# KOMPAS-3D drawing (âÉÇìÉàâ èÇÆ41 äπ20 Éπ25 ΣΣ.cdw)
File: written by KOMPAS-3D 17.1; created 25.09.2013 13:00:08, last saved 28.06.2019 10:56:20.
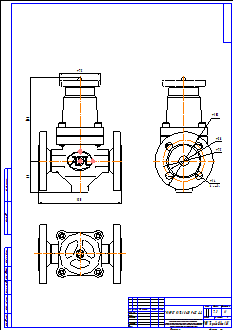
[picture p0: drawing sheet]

Sheet 1: A2, portrait

Title block, sheet 1: name: ГРАНРЕГ КАТ41 Ду20 Ру25 фф; material: Внимание! Данный продукт является объектом авторского права ООО «Торговый Дом АДЛ». / Запрещается изменение, копирование, распространение / (в том числе путем копирования на другие сайты и ресурсы в Интернете) / или любое иное использование информации и объектов без предварительного / согласия правообладателя (ООО «Торговый Дом АДЛ»).; mass: 7,3; sheets: 1; organisation: ООО "Торговый дом АДЛ"; sheet format: A2; stored path: \\adlc.lan\data\АДЛ_ПКД\3D-модели\ADL production\Клапаны КАТ ГРАНРЕГ\КАТ41\KOMPAS 2D\ГРАНРЕГ КАТ41 Ду20 Ру25 фф.cdw

Views: Вид 1, Проекционный вид 2
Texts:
  Klimkovich
  ADL
Dimensions and other numbers on the sheet: 75; 150; 57; 105; 58; 14; 4 отв.; 1:1; 1; 7,3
